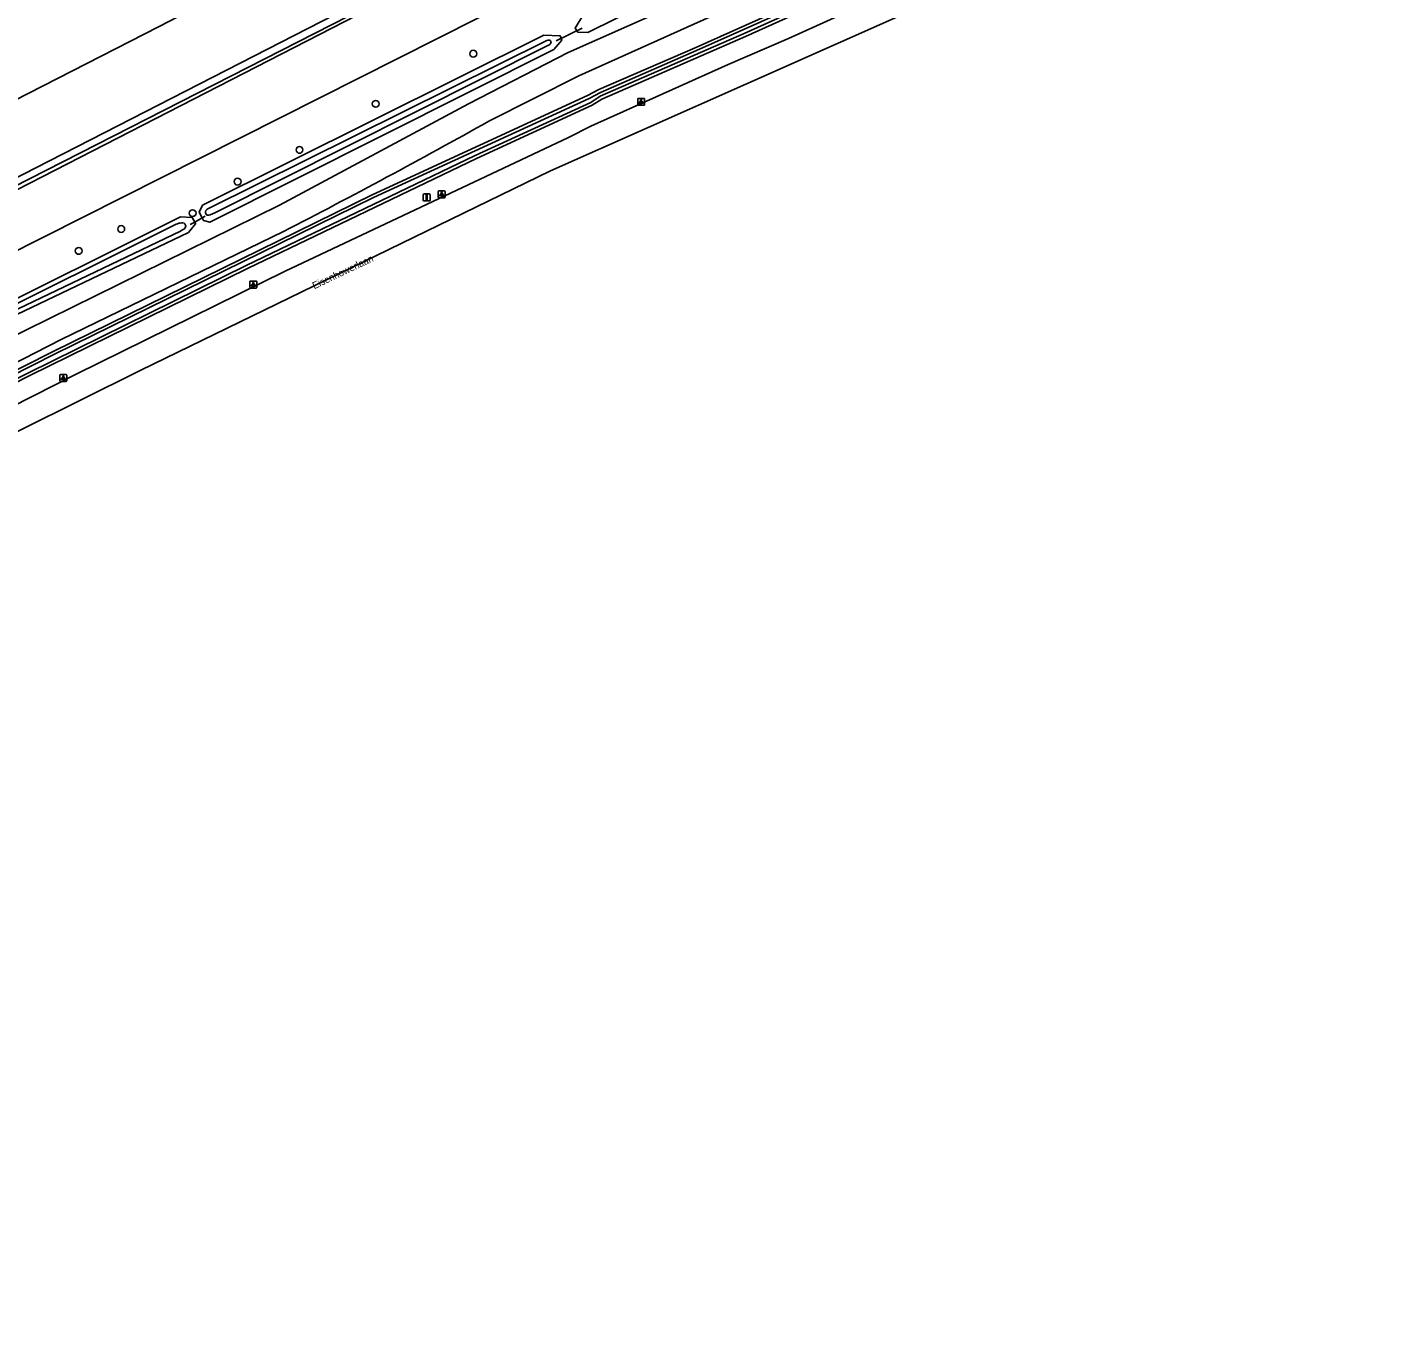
# Model space of a CAD drawing. Extents: x 162722 to 165099, y 384721 to 386283.
# Drawn here: x 164061.3 to 164257.5, y 384775.7 to 384964.6 of the extents above; entities that cross this region are included whole.
import ezdxf

# ---------------------------------------------------------------- set-up
doc = ezdxf.new("R2010")
doc.units = 0
for name, color, linetype in [('IMGEO_Berm_groen', 7, 'Continuous'), ('IMGEO_Boom', 7, 'Continuous'), ('IMGEO_Duiker', 7, 'Continuous'), ('IMGEO_Erf', 7, 'Continuous'), ('IMGEO_Fietspad_gesloten', 7, 'Continuous'), ('IMGEO_Groenvoorziening', 7, 'Continuous'), ('IMGEO_Hek', 7, 'Continuous'), ('IMGEO_Lichtpunt', 7, 'Continuous'), ('IMGEO_Openbare_ruimte_label', 7, 'Continuous'), ('IMGEO_Rijbaan_regionaal_gesloten', 7, 'Continuous'), ('IMGEO_Verkeersbordpaal', 7, 'Continuous'), ('IMGEO_Waterloop', 7, 'Continuous')]:
    doc.layers.add(name, color=color, linetype=linetype)

msp = doc.modelspace()

# ---------------------------------------------------------------- linework, layer by layer
at = {"layer": 'IMGEO_Berm_groen'}
for points in [[(164182.29, 385003.98), (164161.64, 384993.22), (164156.4, 384989.2), (164154.23, 384980.18), (163995.61, 384900.16), (163985.45, 384906.25), (163959.71, 384893.04), (163931.56, 384878.59), (163923.16, 384882.98), (163812.86, 384826.88), (163815.44, 384820.08), (163815.18, 384817.09), (163814.5, 384814.34), (163812.89, 384811.78), (163810.69, 384809.88), (163807.77, 384808.95), (163804.96, 384808.68), (163802.16, 384809.85), (163799.68, 384811.72), (163798.18, 384813.59), (163789.43, 384831.04)], [(163807.89, 384780.49), (163820.58, 384786.08), (163833.81, 384792.71), (163845.03, 384798.67), (163914.44, 384836.89), (163949.64, 384856.5), (163973.82, 384869.78), (164000, 384884.15), (164013.24, 384891.06), (164022.23, 384895.94), (164051.68, 384911.3), (164065.07, 384918.06), (164110.83, 384940.54), (164141.78, 384954.8), (164143.41, 384955.64), (164157.25, 384961.66), (164184.98, 384974.1), (164189.83, 384976.41), (164193.58, 384977.81), (164199.17, 384980.36), (164206.03, 384983.51), (164212.73, 384986.25), (164221.34, 384989.2), (164225.31, 384990.8)], [(164228.52, 384990.48), (164225.9, 384989.38), (164214.03, 384984.88), (164199.86, 384979.03), (164194.07, 384976.64), (164190.41, 384974.99), (164164.46, 384963.29), (164143.81, 384954.27), (164142.44, 384953.4), (164125.83, 384945.72), (164092.92, 384929.94), (164061.64, 384914.53), (164036.12, 384901.56), (164011.74, 384888.67), (164000, 384882.3), (163974.59, 384868.52), (163970.14, 384866.1), (163854.54, 384802.2), (163834.33, 384791.25), (163820.77, 384784.53), (163800.9, 384775.69)], [(164184.89, 384985.15), (164186.11, 384986.84), (164185.86, 384987.37), (164183.73, 384987.45), (164141.09, 384966.28), (164140, 384964.46), (164140.35, 384963.9), (164141.8, 384963.83), (164184.89, 384985.15)], [(164136.94, 384961.41), (164138.06, 384962.73), (164137.83, 384963.37), (164135.48, 384963.47), (164086.45, 384939.03), (164085.98, 384938.02), (164086.39, 384937.19), (164086.57, 384936.81), (164087.47, 384936.57), (164136.94, 384961.41)], [(164084.41, 384935.1), (164085.45, 384936.37), (164085.32, 384936.61), (164084.97, 384937.24), (164083.29, 384937.36), (164052.41, 384921.99), (164052.11, 384921.03), (164052.43, 384920.46), (164053.29, 384920.23), (164084.41, 384935.1)]]:
    msp.add_lwpolyline(points, dxfattribs=at)
at = {"layer": 'IMGEO_Boom'}
for centre in [(164125.35, 384960.8), (164111.33, 384953.6), (164100.38, 384946.98), (164091.49, 384942.42), (164085.02, 384937.88), (164074.76, 384935.6), (164068.65, 384932.46)]:
    msp.add_circle(centre, 0.489, dxfattribs=at)
at = {"layer": 'IMGEO_Duiker'}
for points in [[(164137.26, 384962.65), (164141.01, 384964.48)], [(164086.84, 384937.43), (164086.39, 384937.19), (164085.32, 384936.61), (164084.66, 384936.26)]]:
    msp.add_lwpolyline(points, dxfattribs=at)
at = {"layer": 'IMGEO_Erf'}
msp.add_lwpolyline([(163897.99, 384886.85), (163925.71, 384900.92), (163932.38, 384900.52), (163958.54, 384912.86), (163988.04, 384927.89), (163995.38, 384923.27), (164000, 384925.38), (164021.24, 384935.11), (164050.97, 384949.76), (164080.21, 384964.72), (164134.64, 384992.97), (164135.3, 385000), (164135.49, 385001.97), (164139.93, 385003.08), (164145.22, 385006.02), (164162.18, 385013.17)], dxfattribs=at)
at = {"layer": 'IMGEO_Fietspad_gesloten'}
for points in [[(164257.46, 385008.9), (164236.92, 385000), (164226.46, 384995.47), (164223.85, 384994.34), (164174.93, 384973.13), (164140.51, 384957.62), (164127.58, 384951.11)], [(163837.76, 384799.98), (163968.38, 384872.1), (163971.4, 384873.74), (164000, 384889.27), (164029.89, 384905.3), (164057.85, 384919.48), (164097.49, 384939.03), (164124.66, 384953.58), (164138.96, 384960.97), (164173.57, 384976.37), (164186.77, 384982.11)], [(164098.08, 384935.25), (164066.13, 384919.71), (164027.89, 384900.14), (164000, 384885.24), (163973.26, 384870.69), (163972.15, 384870.08), (163829.91, 384791.63), (163819, 384786.53), (163812.21, 384783.62)]]:
    msp.add_lwpolyline(points, dxfattribs=at)
msp.add_arc((163681.26, 385745.97), 911.6, 297.20884, 299.3146, dxfattribs=at)
at = {"layer": 'IMGEO_Groenvoorziening'}
for points in [[(163804.05, 384830.64), (163923.55, 384891.19), (163932.65, 384886.86), (163985.84, 384913.52), (163996.46, 384908.76), (164000, 384910.58), (164144.89, 384984.96), (164146.02, 384985.93)], [(164146.02, 384985.93), (163996.45, 384909.62), (163986.31, 384914.57), (163955.99, 384899.17), (163932.76, 384887.38), (163923.64, 384892.04), (163901.15, 384880.61)], [(163996.84, 384910.77), (164000, 384912.39), (164142.61, 384985.49)]]:
    msp.add_lwpolyline(points, dxfattribs=at)
at = {"layer": 'IMGEO_Hek'}
for points in [[(164182.29, 385003.98), (164161.64, 384993.22), (164156.4, 384989.2), (164154.23, 384980.18), (163995.61, 384900.16)], [(163955.99, 384899.17), (163986.31, 384914.57), (163996.45, 384909.62), (164146.02, 384985.93)]]:
    msp.add_lwpolyline(points, dxfattribs=at)
at = {"layer": 'IMGEO_Lichtpunt'}
for p, q in [((164148.97, 384954.29), (164148.97, 384953.48)), ((164148.97, 384954.29), (164148.97, 384953.48)), ((164149.88, 384954.38), (164149.07, 384954.38)), ((164149.88, 384954.38), (164149.07, 384954.38)), ((164149.07, 384953.39), (164149.88, 384953.39)), ((164149.07, 384953.39), (164149.88, 384953.39)), ((164149.97, 384953.48), (164149.97, 384954.29)), ((164149.97, 384953.48), (164149.97, 384954.29)), ((164120.31, 384940.99), (164120.31, 384940.18)), ((164120.31, 384940.99), (164120.31, 384940.18)), ((164121.21, 384941.09), (164120.41, 384941.09)), ((164121.21, 384941.09), (164120.41, 384941.09)), ((164120.41, 384940.09), (164121.21, 384940.09)), ((164120.41, 384940.09), (164121.21, 384940.09)), ((164121.31, 384940.18), (164121.31, 384940.99)), ((164121.31, 384940.18), (164121.31, 384940.99)), ((164093.25, 384928.02), (164093.25, 384927.21)), ((164093.25, 384928.02), (164093.25, 384927.21)), ((164094.15, 384928.11), (164093.35, 384928.11)), ((164094.15, 384928.11), (164093.35, 384928.11)), ((164094.25, 384927.21), (164094.25, 384928.02)), ((164094.25, 384927.21), (164094.25, 384928.02)), ((164093.35, 384927.12), (164094.15, 384927.12)), ((164093.35, 384927.12), (164094.15, 384927.12)), ((164065.95, 384914.6), (164065.95, 384913.79)), ((164065.95, 384914.6), (164065.95, 384913.79)), ((164066.85, 384914.69), (164066.04, 384914.69)), ((164066.85, 384914.69), (164066.04, 384914.69)), ((164066.94, 384913.79), (164066.94, 384914.6)), ((164066.94, 384913.79), (164066.94, 384914.6)), ((164066.04, 384913.7), (164066.85, 384913.7)), ((164066.04, 384913.7), (164066.85, 384913.7))]:
    msp.add_line(p, q, dxfattribs=at)
for points in [[(164149.35, 384953.95), (164149.39, 384953.92), (164149.2, 384953.66), (164149.16, 384953.69), (164149.35, 384953.95)], [(164149.45, 384953.9), (164149.5, 384953.9), (164149.5, 384953.58), (164149.45, 384953.58), (164149.45, 384953.9)], [(164149.56, 384953.92), (164149.6, 384953.95), (164149.78, 384953.69), (164149.75, 384953.66), (164149.56, 384953.92)], [(164120.69, 384940.65), (164120.72, 384940.63), (164120.54, 384940.36), (164120.5, 384940.39), (164120.69, 384940.65)], [(164120.79, 384940.61), (164120.83, 384940.61), (164120.83, 384940.28), (164120.79, 384940.28), (164120.79, 384940.61)], [(164120.9, 384940.63), (164120.94, 384940.65), (164121.12, 384940.39), (164121.08, 384940.36), (164120.9, 384940.63)], [(164093.63, 384927.68), (164093.66, 384927.65), (164093.48, 384927.39), (164093.44, 384927.42), (164093.63, 384927.68)], [(164093.73, 384927.63), (164093.78, 384927.63), (164093.78, 384927.31), (164093.73, 384927.31), (164093.73, 384927.63)], [(164093.84, 384927.65), (164093.88, 384927.68), (164094.06, 384927.42), (164094.02, 384927.39), (164093.84, 384927.65)], [(164066.32, 384914.26), (164066.36, 384914.24), (164066.17, 384913.97), (164066.13, 384914), (164066.32, 384914.26)], [(164066.42, 384914.22), (164066.47, 384914.22), (164066.47, 384913.89), (164066.42, 384913.89), (164066.42, 384914.22)], [(164066.53, 384914.24), (164066.57, 384914.26), (164066.76, 384914), (164066.72, 384913.97), (164066.53, 384914.24)]]:
    msp.add_lwpolyline(points, dxfattribs=at)
for centre in [(164149.47, 384954.09), (164120.81, 384940.79), (164093.75, 384927.82), (164066.45, 384914.4)]:
    msp.add_circle(centre, 0.0994, dxfattribs=at)
for centre, start, end in [((164149.07, 384954.29), 90, 180), ((164149.07, 384954.29), 90, 180), ((164149.07, 384953.48), 180, 270), ((164149.07, 384953.48), 180, 270), ((164149.88, 384954.29), 0, 90), ((164149.88, 384954.29), 0, 90), ((164149.88, 384953.48), 270, 0), ((164149.88, 384953.48), 270, 360), ((164120.41, 384940.99), 90, 180), ((164120.41, 384940.99), 90, 180), ((164120.41, 384940.18), 180, 270), ((164120.41, 384940.18), 180, 270), ((164121.21, 384940.99), 0, 90), ((164121.21, 384940.99), 0, 90), ((164121.21, 384940.18), 270, 0), ((164121.21, 384940.18), 270, 360), ((164093.35, 384928.02), 90, 180), ((164093.35, 384928.02), 90, 180), ((164094.15, 384928.02), 0, 90), ((164094.15, 384928.02), 0, 90), ((164093.35, 384927.21), 180, 270), ((164093.35, 384927.21), 180, 270), ((164094.15, 384927.21), 270, 0), ((164094.15, 384927.21), 270, 360), ((164066.04, 384914.6), 90, 180), ((164066.04, 384914.6), 90, 180), ((164066.85, 384914.6), 0, 90), ((164066.85, 384914.6), 0, 90), ((164066.04, 384913.79), 180, 270), ((164066.04, 384913.79), 180, 270), ((164066.85, 384913.79), 270, 0), ((164066.85, 384913.79), 270, 360)]:
    msp.add_arc(centre, 0.0946, start, end, dxfattribs=at)
at = {"layer": 'IMGEO_Rijbaan_regionaal_gesloten'}
for points in [[(163832.08, 384786.73), (163976.2, 384865.89), (163988.46, 384872.63), (164000, 384879.09), (164010.01, 384884.53), (164040.03, 384900.42), (164068.3, 384914.74), (164098.31, 384929.57), (164139.04, 384948.77), (164142.26, 384950.4), (164161.97, 384959.27), (164170.65, 384962.99), (164191.19, 384972.35), (164201.18, 384976.5)], [(164202.85, 384973.28), (164189.76, 384967.64), (164164.51, 384956.41), (164136.45, 384943.99), (164077.48, 384915.27), (164051.63, 384902.41), (163978.15, 384862.7), (163978.1, 384862.67), (163880.93, 384809.18), (163846.96, 384790.27), (163834.09, 384783.25)]]:
    msp.add_lwpolyline(points, dxfattribs=at)
at = {"layer": 'IMGEO_Verkeersbordpaal'}
for p, q in [((164118.15, 384939.75), (164118.15, 384940.54)), ((164118.15, 384940.54), (164118.15, 384939.75)), ((164118.25, 384940.64), (164119.04, 384940.64)), ((164119.04, 384940.64), (164118.25, 384940.64)), ((164119.04, 384939.65), (164118.25, 384939.65)), ((164118.25, 384939.65), (164119.04, 384939.65)), ((164119.14, 384940.54), (164119.14, 384939.75)), ((164119.14, 384939.75), (164119.14, 384940.54))]:
    msp.add_line(p, q, dxfattribs=at)
msp.add_lwpolyline([(164118.57, 384940.52), (164118.72, 384940.52), (164118.72, 384939.77), (164118.57, 384939.77), (164118.57, 384940.52)], dxfattribs=at)
for centre, start, end in [((164118.25, 384940.54), 90, 180), ((164118.25, 384940.54), 90, 180), ((164118.25, 384939.75), 180, 270), ((164118.25, 384939.75), 180, 270), ((164119.04, 384940.54), 0, 90), ((164119.04, 384940.54), 360, 90), ((164119.04, 384939.75), 270, 0), ((164119.04, 384939.75), 270, 0)]:
    msp.add_arc(centre, 0.1, start, end, dxfattribs=at)
at = {"layer": 'IMGEO_Waterloop'}
for points in [[(164247.93, 385001.15), (164247.81, 385001.05), (164246.63, 385000.41), (164239.66, 384996.63), (164234.06, 384993.62), (164228.34, 384990.91), (164225.72, 384989.81), (164213.86, 384985.31), (164199.68, 384979.46), (164193.88, 384977.07), (164190.22, 384975.42), (164164.27, 384963.72), (164143.6, 384954.68), (164142.22, 384953.81), (164125.64, 384946.15), (164092.72, 384930.35), (164061.43, 384914.95), (164035.9, 384901.98)], [(164051.89, 384910.89), (164065.27, 384917.65), (164111.02, 384940.12), (164141.99, 384954.38), (164143.61, 384955.22), (164157.43, 384961.24), (164185.17, 384973.68), (164190.01, 384975.98), (164193.76, 384977.38), (164199.36, 384979.94), (164206.21, 384983.08), (164212.9, 384985.82), (164221.51, 384988.77), (164225.49, 384990.38), (164228.1, 384991.49), (164233.87, 384994.19), (164239.49, 384997.16), (164243.99, 384999.59), (164247.66, 385001.56)], [(164135.91, 384962.7), (164087.39, 384938.61), (164087.21, 384938.51), (164087.05, 384938.4), (164086.92, 384938.28), (164086.85, 384938.09)], [(164087.37, 384937.59), (164087.55, 384937.65), (164088.23, 384937.94), (164136.07, 384961.96)], [(164136.07, 384961.96), (164136.17, 384962.01), (164136.28, 384962.08)], [(164136.52, 384962.51), (164136.5, 384962.58), (164136.38, 384962.7), (164136.3, 384962.74)], [(164083.68, 384935.53), (164083.49, 384935.42), (164083.29, 384935.31), (164053.22, 384920.94), (164052.88, 384921.03), (164052.84, 384921.1), (164052.97, 384921.51), (164082.67, 384936.3)], [(164083.81, 384936.44), (164083.91, 384936.36), (164084.02, 384936.14), (164084.04, 384936.03), (164083.96, 384935.79)]]:
    msp.add_lwpolyline(points, dxfattribs=at)
for centre, radius, start, end in [((164136.15, 384962.2), 0.552, 74.8346, 116.5576), ((164135.99, 384962.52), 0.533, 303.2012, 358.4871), ((164087.37, 384938.05), 0.524, 175.7334, 235.0221), ((164087.26, 384938.03), 0.457, 245.1233, 283.9065), ((164083.72, 384933.72), 2.79, 96.3053, 112.1649), ((164083.51, 384935.75), 0.75, 66.8924, 97.3414), ((164083.22, 384936.31), 0.908, 300.5725, 324.998)]:
    msp.add_arc(centre, radius, start, end, dxfattribs=at)

# ---------------------------------------------------------------- texts
at = {"layer": 'IMGEO_Openbare_ruimte_label'}
msp.add_text('Eisenhowerlaan', height=1, rotation=25.4116, dxfattribs=at).set_placement((164102.51, 384926.94))

doc.saveas('drawing.dxf')
